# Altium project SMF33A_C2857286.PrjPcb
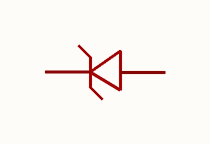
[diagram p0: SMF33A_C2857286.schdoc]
1 sheet, 1 parts. Net scope: global (net labels, ports and power ports of the same name join across sheets).

## Sheet SMF33A_C2857286.schdoc
size 127 x 101 mm

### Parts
D?  smf33a_c2857286  [SOD-123FL_L2.8-W1.8-LS3.6-RD]  (value not drawn)

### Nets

Not connected (* = marked no-connect by the designer): D? 1(C) 2(A)

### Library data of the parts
D? = smf33a_c2857286: 极性:单向;反向截止电压(Vrwm):33V;钳位电压:53.3V;峰值脉冲电流(Ipp):3.8A;峰值脉冲功率(Ppp):200W@10/1000us;击穿电压(VBR):36.7V;; Manufacturer: JSMSEMI(杰盛微); ManufacturerPart: SMF33A; AddInBom: yes; ModelId: 9a6bf0a398604d2998ad78800a7c8ef9; ModelTransform: 141.732,70.866,0,0,0,0,0,0,0; Polarity: 单向; Reverse Stand-Off Voltage (Vrwm): 33V; Clamping Voltage: 53.3V; Peak Pulse Current (Ipp): 3.8A; Voltage - Breakdown: 36.7V; Reverse Leakage Current (Ir): 1uA; Number of Channels: 单路; Type: TVS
